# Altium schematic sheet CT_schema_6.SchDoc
size 278 x 170 mm
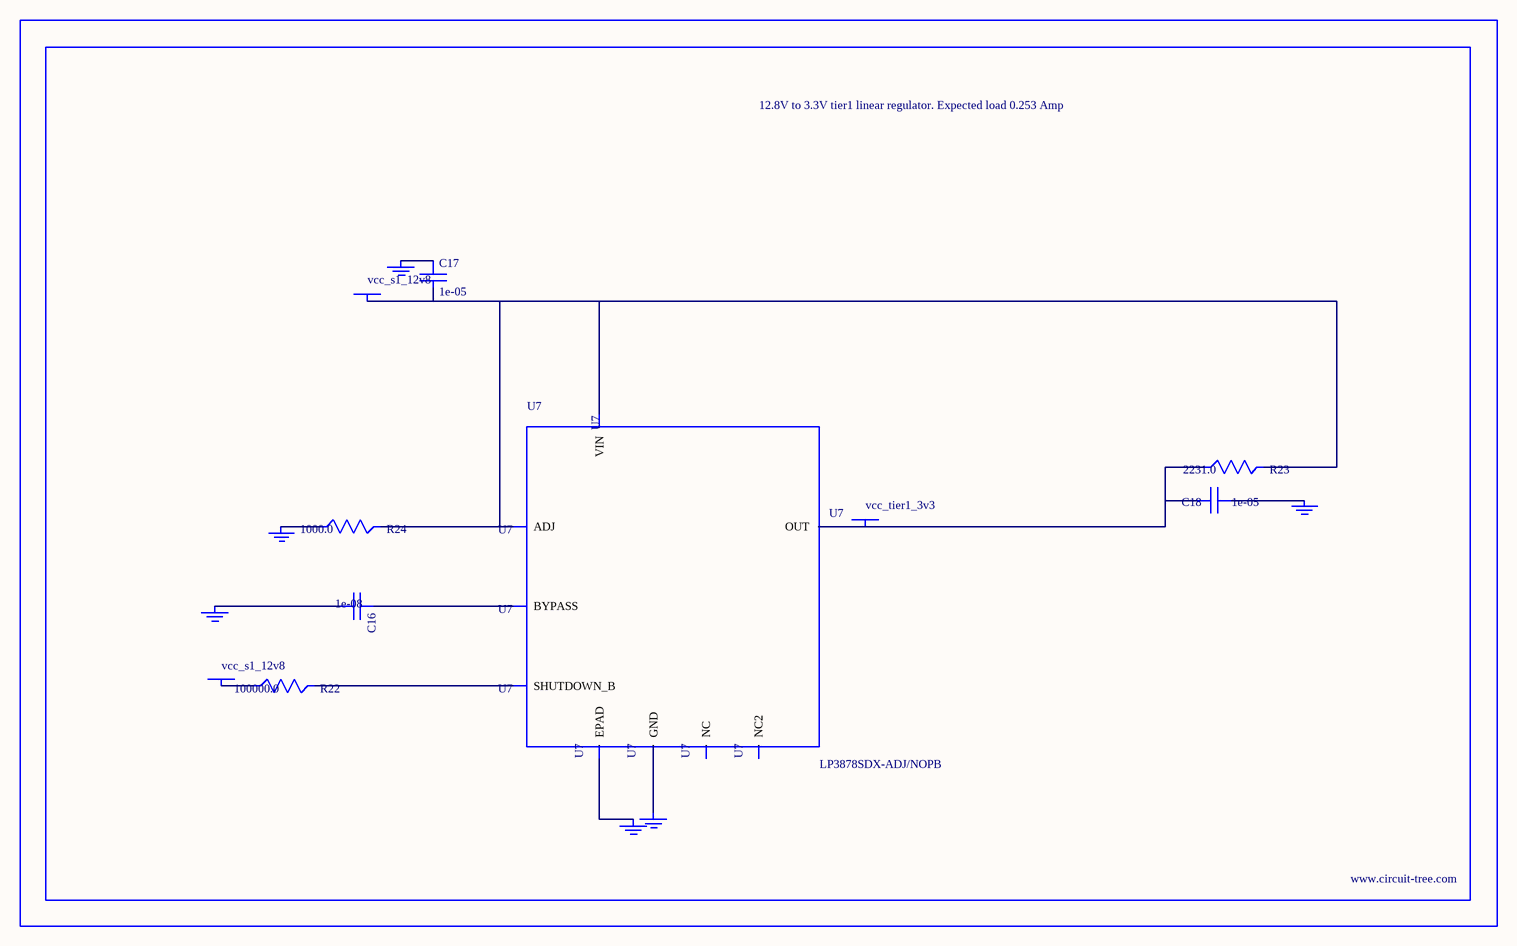
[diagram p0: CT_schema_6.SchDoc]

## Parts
BORDER5  (no value)
C16  1e-08  [C0402]
C17  1e-05  [C1210]
C18  1e-05  [C1210]
GND_INSTANCE_5_0  (no value)
GND_INSTANCE_5_1  (no value)
GND_INSTANCE_5_2  (no value)
GND_INSTANCE_5_3  (no value)
GND_INSTANCE_5_4  (no value)
GND_INSTANCE_5_5  (no value)
POWER_INSTANCE_5_0  vcc_s1_12v8
POWER_INSTANCE_5_1  vcc_s1_12v8
POWER_INSTANCE_5_2  vcc_tier1_3v3
R22  100000.0  [R0603]
R23  2231.0  [R0603]
R24  1000.0  [R0603]
U7  LP3878SDX-ADJ/NOPB  [WSON-8]

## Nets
NetC16_1: C16.1 U7.1(BYPASS)
NetC16_2: C16.2 GND_INSTANCE_5_0.0(GND)
NetC17_1: C17.1 GND_INSTANCE_5_1.0(GND)
NetC17_2: C17.2 POWER_INSTANCE_5_0.0(PWR) R23.2 R24.2 U7.4(VIN) U7.6(ADJ)
NetC18_1: C18.1 GND_INSTANCE_5_2.0(GND)
NetC18_2: C18.2 POWER_INSTANCE_5_2.0(PWR) R23.1 U7.5(OUT)
NetGND_INSTANCE_5_3_0: GND_INSTANCE_5_3.0(GND) R24.1
NetGND_INSTANCE_5_4_0: GND_INSTANCE_5_4.0(GND) U7.PAD(EPAD)
NetGND_INSTANCE_5_5_0: GND_INSTANCE_5_5.0(GND) U7.3(GND)
NetPOWER_INSTANCE_5_1_0: POWER_INSTANCE_5_1.0(PWR) R22.1
NetR22_2: R22.2 U7.8(SHUTDOWN_B)

Not connected (* = marked no-connect by the designer): U7 2(NC) 7(NC2)

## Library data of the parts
BORDER5 = BORDER_PAGE5
C16 = C0402C103K3RAC
C17 = C1210C106K5PACTU
C18 = GRM32DR61E106MA12L
GND_INSTANCE_5_0-GND_INSTANCE_5_5 = GND
POWER_INSTANCE_5_0-POWER_INSTANCE_5_2 = PWR
R22 = RC0603JR-07100KL
R23 = R23
R24 = RC0603JR-071KL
